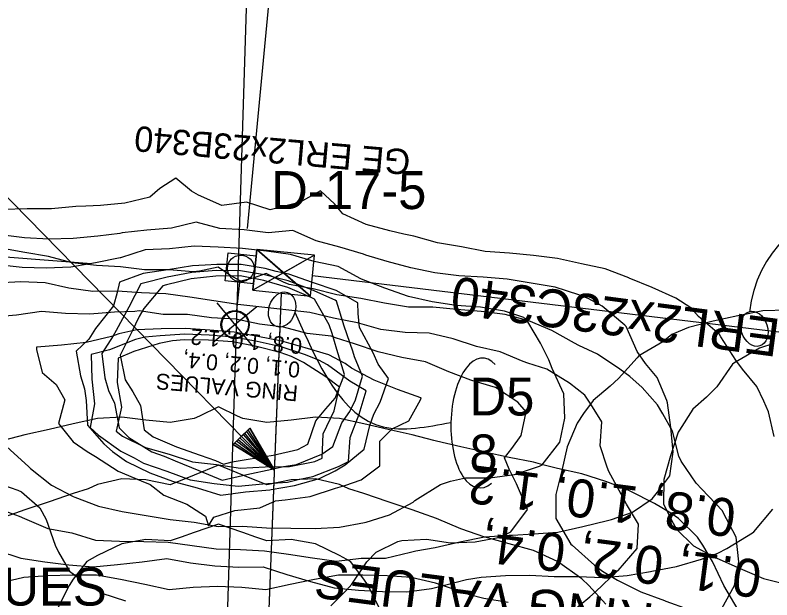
# Model space of a CAD drawing. Extents: x 1638506 to 1658005, y 834807 to 846788.
# Drawn here: x 1642396.4 to 1642635.4, y 842263.3 to 842448.1 of the extents above; entities that cross this region are included whole.
import ezdxf

# ---------------------------------------------------------------- set-up
doc = ezdxf.new("R2010")
doc.units = 0
for name, color, linetype in [('Default', 7, 'Continuous'), ('Old_Level_1', 7, 'Continuous'), ('Old_Level_2', 7, 'Continuous'), ('Scratch_Level_0', 7, 'Continuous')]:
    doc.layers.add(name, color=color, linetype=linetype)

msp = doc.modelspace()

# ---------------------------------------------------------------- linework, layer by layer
at = {"layer": 'Default'}
for p, q in [((1642469.76, 842380.62), (1642481.25, 842500.55)), ((1642342.93, 842442.48), (1642478.26, 842304.41)), ((1642490.95, 842372.22), (1642471.46, 842361.16)), ((1642489.65, 842359.32), (1642472.76, 842374.05)), ((1642490.3, 842365.77), (1642742.03, 842335.36)), ((1642467.21, 842363.62), (1642466.31, 842354.72)), ((1642473.12, 842172.77), (1642480.55, 842360.24)), ((1642472.77, 842355.93), (1642458.93, 842344.63)), ((1642471.53, 842343.36), (1642460.2, 842357.2)), ((1642469.35, 842353.14), (1642469.35, 842353.14)), ((1642465.86, 842350.27), (1642465.86, 842350.27)), ((1642473.28, 842176.7), (1642480.22, 842351.8))]:
    msp.add_line(p, q, dxfattribs=at)
for points in [[(1642472.55, 842372.04), (1642471.66, 842363.17), (1642462.76, 842364.07), (1642463.65, 842372.94)], [(1642490.95, 842372.22), (1642472.76, 842374.05), (1642471.46, 842361.16), (1642489.65, 842359.32)], [(1642481.2, 842366.69), (1642471.46, 842361.16), (1642472.76, 842374.05)], [(1642481.2, 842366.69), (1642489.65, 842359.32), (1642490.95, 842372.22)]]:
    msp.add_lwpolyline(points, close=True, dxfattribs=at)
msp.add_lwpolyline([(1642467.9, 842314.98), (1642468.43, 842315.5), (1642478.26, 842304.41), (1642468.92, 842315.98), (1642469.45, 842316.5), (1642478.26, 842304.41), (1642469.98, 842317.02), (1642470.51, 842317.53), (1642478.26, 842304.41), (1642465.3, 842312.36), (1642465.79, 842312.91), (1642478.26, 842304.41), (1642466.35, 842313.39), (1642466.85, 842313.94), (1642478.26, 842304.41), (1642467.37, 842314.46), (1642470.51, 842317.53), (1642465.3, 842312.36), (1642478.26, 842304.41), (1642470.51, 842317.53)], dxfattribs=at)
msp.add_circle((1642465.86, 842350.3), 4.47, dxfattribs=at)
for centre, major_axis, ratio, start_param, end_param in [((1642658, 842350.99), (-3.78, -34.34), 0.862742, 3.141593, 4.712389), ((1642543.62, 842319.15), (-0.49, -20.52), 0.466223, 2.710831, 4.712389), ((1642543.62, 842319.15), (-0.49, -20.52), 0.466223, 4.712389, 6.681485)]:
    msp.add_ellipse(centre, major_axis=major_axis, ratio=ratio, start_param=start_param, end_param=end_param, dxfattribs=at)
for centre, major_axis in [((1642480.71, 842355.05), (1.72, 5.4)), ((1642629.94, 842348.95), (1.72, -5.4))]:
    msp.add_ellipse(centre, major_axis=major_axis, ratio=0.730797, dxfattribs=at)
msp.add_spline([(1642484.79, 842354.24), (1642512.62, 842317.96), (1642534.05, 842319.37)], degree=3, dxfattribs=at)
at = {"layer": 'Old_Level_1'}
for points in [[(1642636.21, 842314.91), (1642634.39, 842322.75), (1642632.93, 842326.11), (1642630.72, 842330.75), (1642626.13, 842336.15), (1642624.01, 842339.02), (1642619.35, 842346.46), (1642618.9, 842347.14), (1642612.23, 842352.84), (1642609.85, 842355.61), (1642605.06, 842358.67), (1642597.68, 842362.03), (1642590.31, 842365), (1642590.26, 842365.02), (1642582.83, 842367.91), (1642575.29, 842369.54), (1642567.75, 842371.13), (1642560.16, 842372.13), (1642552.55, 842372.84), (1642544.91, 842373.35), (1642537.36, 842374.85), (1642529.8, 842376.17), (1642522.3, 842378.24), (1642519.22, 842378.9), (1642514.77, 842379.93), (1642507.27, 842381.97), (1642499.88, 842385.29), (1642497.26, 842388.5), (1642492.84, 842392.62), (1642487.21, 842389.38), (1642484.8, 842388.53), (1642476.96, 842386.61), (1642469.48, 842388.96), (1642461.72, 842387.94), (1642454.32, 842391.19), (1642452.1, 842392.45), (1642447.12, 842396.62), (1642442.05, 842393.33), (1642438.91, 842390.62), (1642431.06, 842388.64), (1642423.32, 842387.93), (1642418.76, 842387.69), (1642415.61, 842387.57), (1642407.86, 842386.84), (1642400.19, 842386.86), (1642392.49, 842386.69)], [(1642391.88, 842291.85), (1642397.64, 842289.71), (1642399.3, 842288.97), (1642406.7, 842285.78), (1642414.26, 842284.44), (1642421.74, 842282.13), (1642429.4, 842281.83), (1642437.06, 842281.68), (1642444.72, 842281.45), (1642452.31, 842280.47), (1642459.9, 842279.41), (1642467.56, 842279.14), (1642475.2, 842278.79), (1642482.79, 842277.68), (1642490.36, 842276.5), (1642497.95, 842275.46), (1642505.71, 842276.43), (1642513.39, 842276.44), (1642521.24, 842278.3), (1642523, 842278.74), (1642529.05, 842279.85), (1642536.89, 842281.65), (1642544.7, 842283.16), (1642552.42, 842283.66), (1642553.54, 842283.75), (1642560.14, 842284.14), (1642567.87, 842284.68), (1642575.7, 842286.46), (1642583.55, 842288.38), (1642584.82, 842288.69), (1642591.46, 842290.98), (1642597.65, 842295.25), (1642599.73, 842297.8), (1642603.17, 842302.44), (1642604.31, 842310.02), (1642603.54, 842317.77), (1642602.51, 842325.54), (1642602.23, 842326.27), (1642599.17, 842333.51), (1642595.57, 842337.97), (1642592.9, 842341.74), (1642589.38, 842349.72), (1642588.95, 842350.12), (1642581.8, 842356.15), (1642577.66, 842358.43), (1642574.44, 842359.73), (1642566.96, 842362.11), (1642559.4, 842363.41), (1642551.83, 842364.63), (1642544.21, 842365.31), (1642536.56, 842365.68), (1642528.97, 842366.65), (1642521.42, 842368.19), (1642513.92, 842370.27), (1642507.13, 842372.28), (1642506.45, 842372.58), (1642498.96, 842374.79), (1642491.46, 842376.8), (1642484.06, 842380.03), (1642476.32, 842379.3), (1642468.72, 842380.26), (1642461.08, 842380.63), (1642453.58, 842382.7), (1642445.73, 842380.8), (1642437.99, 842380.12), (1642430.24, 842379.25), (1642429.51, 842379.07), (1642422.47, 842378.27), (1642414.73, 842377.53), (1642407.03, 842377.32), (1642399.38, 842377.68), (1642391.79, 842378.64)], [(1642393.62, 842311.77), (1642400.74, 842305.35), (1642401.21, 842304.75), (1642407.9, 842299.52), (1642414.69, 842295.89), (1642415.25, 842295.68), (1642422.68, 842292.89), (1642430.21, 842291.16), (1642437.78, 842289.94), (1642445.35, 842288.7), (1642452.96, 842287.87), (1642460.52, 842286.47), (1642468.2, 842286.54), (1642475.84, 842286.03), (1642483.51, 842285.94), (1642491.18, 842285.82), (1642498.89, 842286.22), (1642506.7, 842287.68), (1642507.29, 842287.79), (1642514.6, 842290.18), (1642522.1, 842294.18), (1642522.67, 842294.68), (1642530.79, 842299.77), (1642533.92, 842300.82), (1642538.65, 842301.79), (1642546.34, 842301.86), (1642554.11, 842302.92), (1642562.02, 842305.57), (1642562.93, 842305.96), (1642568.5, 842313.16), (1642570.09, 842320.7), (1642569.7, 842328.41), (1642566.08, 842336.4), (1642564.95, 842339.11), (1642562.31, 842344.41), (1642558.33, 842351.16), (1642557.11, 842352.55), (1642550.94, 842354.51), (1642543.38, 842355.8), (1642535.74, 842356.33), (1642528.16, 842357.43), (1642520.63, 842359.14), (1642513.19, 842361.85), (1642505.76, 842364.68), (1642505.63, 842364.73), (1642498.42, 842368.6), (1642490.89, 842370.26), (1642483.39, 842372.4), (1642475.81, 842373.48), (1642468.2, 842374.31), (1642460.57, 842374.81), (1642452.91, 842375.07), (1642445.16, 842374.26), (1642437.45, 842373.93), (1642429.68, 842371.38), (1642429.55, 842371.34), (1642421.74, 842369.85), (1642413.94, 842368.47), (1642406.22, 842368.09), (1642398.57, 842368.33), (1642390.96, 842369.14)], [(1642416.98, 842334.09), (1642418.25, 842329.97), (1642418.84, 842326.25), (1642419.28, 842318.53), (1642424.41, 842312.61), (1642427.12, 842310.17), (1642431.6, 842306.98), (1642438.96, 842303.37), (1642446.08, 842300.83), (1642446.41, 842300.73), (1642453.91, 842298.71), (1642461.38, 842296.34), (1642469.15, 842297.38), (1642476.89, 842298.06), (1642477.23, 842298.1), (1642484.68, 842299.37), (1642492.56, 842301.65), (1642497.52, 842304.01), (1642500.62, 842305.95), (1642506.69, 842310.88), (1642508.47, 842318.41), (1642509.7, 842321.97), (1642511.66, 842325.81), (1642514.33, 842333.25), (1642511.08, 842337.73), (1642509.52, 842341.35), (1642505.17, 842349.41), (1642504.8, 842353.76), (1642504.65, 842357.14), (1642497.77, 842361.11), (1642490.31, 842363.63), (1642482.85, 842366.21), (1642478.85, 842367.07), (1642475.33, 842367.98), (1642467.77, 842369.32), (1642460.09, 842369.31), (1642456.46, 842369.03), (1642452.37, 842368.88), (1642444.58, 842367.63), (1642436.8, 842366.45), (1642429.32, 842363.73), (1642428.59, 842360.43), (1642427.47, 842356.21), (1642421.79, 842349.03), (1642419.63, 842345.73), (1642415.65, 842341.89), (1642416.98, 842334.09)], [(1642424.68, 842333.42), (1642425.88, 842329.43), (1642427.75, 842325.47), (1642429.23, 842317.66), (1642432.26, 842314.61), (1642439.54, 842310.05), (1642443.48, 842308.73), (1642446.98, 842307.23), (1642454.39, 842304.18), (1642461.8, 842301.13), (1642469.63, 842302.85), (1642477.46, 842304.56), (1642481.16, 842305.44), (1642485.27, 842306.05), (1642493.23, 842309.28), (1642496.74, 842311.75), (1642499.56, 842319.19), (1642502.09, 842322.76), (1642503.96, 842326.48), (1642506.17, 842333.97), (1642503.6, 842340.07), (1642503.06, 842341.92), (1642500.36, 842349.83), (1642497.89, 842357.73), (1642497.49, 842357.96), (1642490.1, 842361.23), (1642482.67, 842364.13), (1642475.16, 842366.01), (1642467.59, 842367.27), (1642459.91, 842367.34), (1642452.19, 842366.79), (1642444.37, 842365.23), (1642436.52, 842363.29), (1642436.09, 842363.14), (1642432.28, 842355.79), (1642428.25, 842348.46), (1642427.39, 842346.74), (1642423.81, 842341.17), (1642424.68, 842333.42)], [(1642431.15, 842332.85), (1642433.52, 842328.98), (1642435.94, 842324.75), (1642437.1, 842316.97), (1642439.96, 842314.8), (1642447.36, 842311.68), (1642454.81, 842309.03), (1642459.7, 842307.32), (1642462.24, 842306.14), (1642464.94, 842306.86), (1642470.05, 842307.69), (1642477.85, 842309.01), (1642485.68, 842310.79), (1642488.88, 842312.44), (1642491.37, 842319.9), (1642494.49, 842323.64), (1642497.49, 842327.05), (1642500.39, 842334.47), (1642498.01, 842342.36), (1642496.57, 842347.49), (1642495.63, 842350.25), (1642490.96, 842358.33), (1642489.88, 842358.82), (1642482.49, 842362.04), (1642475, 842364.25), (1642467.45, 842365.69), (1642459.76, 842365.59), (1642452, 842364.71), (1642444.16, 842362.82), (1642443.01, 842362.53), (1642437.02, 842355.38), (1642435.61, 842352.82), (1642433.3, 842348.02), (1642429.59, 842340.67), (1642431.15, 842332.85)], [(1642640.27, 842354.88), (1642632.57, 842354.59), (1642624.75, 842353.04), (1642624.7, 842353.02), (1642616.93, 842351.38), (1642609.07, 842349.35), (1642603.82, 842347.17), (1642601, 842344.85), (1642593.44, 842340.4), (1642592.88, 842339.81), (1642586.99, 842333.28), (1642584.41, 842330.83), (1642578.95, 842326.31), (1642575.97, 842322.13), (1642573.95, 842319.07), (1642570.79, 842311.66), (1642569.07, 842304.14), (1642567.18, 842296.62), (1642567.24, 842288.94), (1642571.96, 842280.85)], [(1642636.02, 842344.35), (1642631.54, 842342.83), (1642623.45, 842338.14), (1642622.96, 842337.82), (1642618.1, 842330.56), (1642614.82, 842327.32), (1642610.51, 842323.55), (1642606.24, 842316.95), (1642605.83, 842316.28), (1642603.46, 842308.81), (1642601.36, 842301.31), (1642601.17, 842293.65)], [(1642601.17, 842293.65), (1642603.75, 842288.48), (1642605.35, 842285.6), (1642610.71, 842280.33), (1642616.85, 842276.92), (1642618.05, 842276.4), (1642625.44, 842273.14), (1642632.85, 842270.03), (1642640.36, 842268.15)], [(1642390.74, 842278.87), (1642398.21, 842276.45), (1642405.78, 842275.24), (1642413.38, 842274.35), (1642421, 842273.69), (1642428.74, 842274.4), (1642436.5, 842275.31), (1642444.27, 842276.36), (1642451.83, 842274.94), (1642459.42, 842273.98), (1642467.07, 842273.6), (1642474.76, 842273.69), (1642482.23, 842271.31), (1642489.71, 842269.07), (1642497.21, 842267.02), (1642504.83, 842266.35), (1642512.47, 842265.91), (1642520.14, 842265.78), (1642527.92, 842266.87), (1642535.76, 842268.8), (1642539, 842269.66), (1642543.58, 842270.41), (1642551.31, 842270.96), (1642559, 842271.08), (1642566.64, 842270.62), (1642574.32, 842270.68), (1642581.98, 842270.36), (1642589.7, 842270.93), (1642597.06, 842272.26), (1642597.51, 842272.35), (1642605.31, 842273.77), (1642613.2, 842276.13), (1642618.4, 842278.07), (1642621.17, 842279.51), (1642629.29, 842284.49), (1642629.71, 842284.76), (1642635.76, 842291.91)], [(1642571.96, 842280.85), (1642572.33, 842280.5), (1642579.46, 842274.19), (1642581.94, 842272.29), (1642586.72, 842269.48), (1642594.08, 842265.78), (1642601.52, 842263.03), (1642601.94, 842262.86), (1642608.96, 842260.27), (1642616.47, 842258.37), (1642624.06, 842257.35), (1642631.62, 842255.97), (1642639.22, 842255.09)], [(1642552.11, 842262.46), (1642544.46, 842263.68), (1642539.96, 842264.82), (1642536.81, 842265.97), (1642529.16, 842268.57), (1642521.51, 842270.33), (1642513.86, 842270.87), (1642506.21, 842271.1), (1642498.56, 842271.1), (1642490.91, 842269.71), (1642483.26, 842268.13), (1642475.61, 842266.41), (1642467.96, 842267.17), (1642460.31, 842267.46), (1642452.66, 842267.17), (1642445.01, 842266.41), (1642437.36, 842268.13), (1642429.71, 842269.71), (1642422.06, 842271.1), (1642414.41, 842271.1), (1642406.76, 842270.87), (1642399.11, 842270.33), (1642391.46, 842268.57)]]:
    msp.add_lwpolyline(points, dxfattribs=at)
msp.add_circle((1642467.66, 842368.05), 4.21, dxfattribs=at)
at = {"layer": 'Old_Level_2'}
msp.add_line((1642458.82, 842108.44), (1642469.85, 842461.62), dxfattribs=at)
msp.add_lwpolyline([(1642025.39, 842444.99), (1642047.66, 842437.99), (1642090.85, 842425.3), (1642111.35, 842420.03), (1642135.93, 842413.98), (1642180.4, 842403.97), (1642212.86, 842397.26), (1642258.65, 842389.41), (1642289.59, 842384.48), (1642317.7, 842380.48), (1642343.73, 842376.94), (1642368.27, 842374.07), (1642394.7, 842371.65), (1642420.5, 842369.62)], dxfattribs=at)
at = {"layer": 'Scratch_Level_0'}
for points in [[(1642619.64, 842260.56), (1642623.63, 842267.75), (1642625.02, 842275.28), (1642624.13, 842283.12), (1642620.08, 842290.93), (1642619.85, 842291.4), (1642613.34, 842298.29), (1642611.58, 842300.2), (1642606.78, 842307.09), (1642606.09, 842308.64), (1642604.07, 842316.62), (1642601.03, 842322.04), (1642599.35, 842324.96), (1642594.42, 842330.4), (1642590.59, 842333.83), (1642587.46, 842336.17), (1642580.38, 842340.98), (1642574.45, 842343.67), (1642573.11, 842344.38), (1642565.93, 842348.42), (1642558.62, 842351.5), (1642551.16, 842353.45), (1642543.58, 842354.46), (1642535.94, 842355.06), (1642528.32, 842355.81), (1642520.61, 842355.82), (1642513.05, 842357.03), (1642505.54, 842358.58), (1642497.96, 842359.66), (1642490.51, 842361.61), (1642482.97, 842362.99), (1642481.12, 842363.69), (1642475.71, 842366.48), (1642471.57, 842364.95), (1642467.67, 842363.97), (1642464.16, 842365.92), (1642460.55, 842368.47), (1642454.6, 842367.18), (1642452.63, 842366.98), (1642445, 842367.61), (1642437.29, 842367.65), (1642429.69, 842368.57), (1642422.04, 842369.02), (1642414.43, 842369.81), (1642406.97, 842371.8), (1642399.42, 842373.05), (1642391.89, 842374.44)], [(1642571.87, 842259.14), (1642577.98, 842264.21), (1642579.74, 842265.82), (1642586.79, 842272.53), (1642586.86, 842272.59), (1642592.89, 842279.52), (1642593.29, 842287.18), (1642589.56, 842293.56), (1642588.5, 842295.53), (1642583.97, 842303.84), (1642583.38, 842305.19), (1642581.24, 842311.92), (1642581.77, 842319.56), (1642578.3, 842325.17), (1642576.33, 842327.99), (1642571.46, 842331.8), (1642564.32, 842336.19), (1642558.32, 842338.08), (1642556.92, 842338.63), (1642549.61, 842341.69), (1642542.11, 842343.36), (1642534.72, 842345.8), (1642527.23, 842347.53), (1642519.55, 842347.79), (1642511.96, 842348.78), (1642504.52, 842350.87), (1642497, 842352.34), (1642489.51, 842354.07), (1642481.91, 842354.95), (1642474.3, 842355.75), (1642466.71, 842356.69), (1642459.13, 842357.75), (1642451.57, 842358.95), (1642444.01, 842360.06), (1642436.33, 842360.34), (1642428.68, 842360.86), (1642420.95, 842360.77), (1642413.37, 842361.78), (1642405.88, 842363.52), (1642398.2, 842363.79), (1642390.42, 842363.35)], [(1642496.16, 842261.4), (1642501.1, 842266.37), (1642502.7, 842268.25), (1642507.53, 842275.33), (1642510.4, 842278.38), (1642517.33, 842281.76), (1642518.59, 842281.98), (1642526.37, 842282.47), (1642533.93, 842281.26), (1642541.69, 842281.61), (1642549.6, 842283.05), (1642553.03, 842284.77), (1642558.21, 842291.8), (1642554.72, 842299.98), (1642552.44, 842304.59), (1642550.93, 842308.19), (1642553.3, 842311.13), (1642556.23, 842315.21), (1642557.87, 842322.71), (1642555.23, 842325.76), (1642548.13, 842330.43), (1642540.7, 842332.62), (1642540.35, 842332.74), (1642533.34, 842335.32), (1642526.04, 842338.46), (1642518.5, 842339.85), (1642511.02, 842341.63), (1642503.64, 842344.2), (1642497.55, 842346.09), (1642496.25, 842346.62), (1642488.64, 842347.47), (1642481.2, 842349.52), (1642473.61, 842350.47), (1642466.09, 842352.01), (1642458.44, 842352.47), (1642450.86, 842353.52), (1642443.14, 842353.47), (1642435.57, 842354.62), (1642434.18, 842354.44), (1642427.8, 842354.19), (1642420.01, 842353.62), (1642412.32, 842353.84), (1642404.69, 842354.45), (1642396.82, 842353.31), (1642389.37, 842352.63)], [(1642403.1, 842343.1), (1642403.1, 842342.45), (1642404.95, 842335.15), (1642409.36, 842331.35), (1642412.13, 842326.48), (1642410.1, 842319.03), (1642414.68, 842313.19), (1642419.18, 842310.12), (1642421.79, 842308.59), (1642428.9, 842303.97), (1642436.21, 842300.87), (1642439.09, 842299.78), (1642443.33, 842296.4), (1642450.67, 842293.55), (1642456.55, 842289.77), (1642457.48, 842286.69), (1642459.18, 842289.42), (1642465.84, 842291.55), (1642473.67, 842292.4), (1642478.64, 842294.57), (1642481.71, 842294.88), (1642489.57, 842295.98), (1642497.63, 842298.59), (1642500.55, 842299.4), (1642505.69, 842301.2), (1642511.63, 842305.66), (1642511.59, 842313.38), (1642515.54, 842317.36), (1642520.78, 842319.88), (1642524.45, 842326.46), (1642524.63, 842327.09), (1642524.54, 842327.14), (1642517.18, 842329.79), (1642509.84, 842332.67), (1642502.63, 842336.54), (1642500.64, 842337.97), (1642495.46, 842340.69), (1642488.05, 842342.96), (1642480.61, 842345.09), (1642473.08, 842346.48), (1642465.54, 842347.84), (1642457.91, 842348.48), (1642450.28, 842349.09), (1642442.54, 842348.96), (1642434.79, 842348.68), (1642429.09, 842347.4), (1642426.79, 842346.53), (1642418.83, 842344.66), (1642411, 842343.78), (1642403.19, 842343.13), (1642403.1, 842343.1)], [(1642420.06, 842317.72), (1642422.68, 842315.37), (1642429.73, 842310.29), (1642433.95, 842308.18), (1642436.94, 842306.47), (1642444.32, 842303.91), (1642451.68, 842301.23), (1642459.24, 842300.04), (1642466.85, 842299.23), (1642474.66, 842299.91), (1642482.45, 842300.47), (1642485.78, 842301.35), (1642490.41, 842302.29), (1642498.53, 842305.37), (1642501.67, 842306.97), (1642502.25, 842314.61), (1642505.1, 842321.95), (1642507.28, 842329.38), (1642502.08, 842332.35), (1642495.05, 842337.55), (1642492.33, 842339.06), (1642487.76, 842340.78), (1642480.38, 842343.3), (1642472.87, 842344.9), (1642465.35, 842346.36), (1642457.7, 842346.9), (1642450.04, 842347.3), (1642442.25, 842346.77), (1642437.4, 842346.3), (1642434.38, 842345.54), (1642426.24, 842342.34), (1642420.44, 842340.82), (1642420.63, 842333.08), (1642421.48, 842325.25), (1642420.06, 842317.72)], [(1642428.34, 842316.63), (1642430.35, 842315.01), (1642437.6, 842311.46), (1642445.04, 842309.36), (1642452.43, 842306.85), (1642460.04, 842306.05), (1642467.59, 842304.85), (1642475.38, 842305.36), (1642483.11, 842305.46), (1642491.03, 842307.02), (1642493.39, 842308.06), (1642493.73, 842315.73), (1642497.16, 842322.99), (1642498.84, 842330.49), (1642494.56, 842333.81), (1642487.44, 842338.35), (1642483.65, 842340.21), (1642480.14, 842341.5), (1642472.66, 842343.33), (1642465.15, 842344.87), (1642457.5, 842345.33), (1642449.8, 842345.5), (1642446.07, 842345.16), (1642441.93, 842344.34), (1642433.88, 842341.81), (1642428.89, 842339.71), (1642428.57, 842332.03), (1642430, 842324.13), (1642428.34, 842316.63)], [(1642624.81, 842260.1), (1642621.29, 842265.98), (1642620.3, 842267.75), (1642616.7, 842275.4), (1642613.64, 842280.54), (1642611.92, 842283.05), (1642605.99, 842288.95), (1642603.56, 842290.7), (1642598.34, 842293.69), (1642590.69, 842297.59), (1642589.11, 842298.35), (1642583.04, 842300.64), (1642575.39, 842303.11), (1642567.74, 842304.74), (1642563.05, 842306), (1642560.09, 842306.81), (1642552.44, 842308.23), (1642544.79, 842309.92), (1642537.14, 842311.62), (1642529.49, 842313.46), (1642528.68, 842313.65), (1642521.84, 842315.38), (1642514.19, 842317.14), (1642506.54, 842318.95), (1642498.89, 842320.56), (1642491.24, 842321.06), (1642483.59, 842320.06), (1642475.94, 842319.37), (1642468.29, 842320.59), (1642466.6, 842321.3), (1642460.64, 842324.28), (1642454.67, 842321.3), (1642452.99, 842320.59), (1642445.34, 842319.37), (1642437.69, 842320.06), (1642430.04, 842321.06), (1642422.39, 842320.56), (1642414.74, 842318.95), (1642407.09, 842317.14), (1642399.44, 842315.38), (1642392.59, 842313.65)], [(1642583.04, 842261.93), (1642577.64, 842267.75), (1642575.39, 842269.87), (1642567.74, 842275.38), (1642567.7, 842275.4), (1642560.09, 842278.9), (1642552.44, 842280.97), (1642544.82, 842283.05), (1642544.79, 842283.06), (1642537.14, 842285.75), (1642529.49, 842288.98), (1642524.74, 842290.7), (1642521.84, 842291.73), (1642514.19, 842294.24), (1642506.54, 842296.88), (1642501.84, 842298.35), (1642498.89, 842299.68), (1642491.24, 842301.47), (1642483.59, 842301.19), (1642475.94, 842299.65), (1642468.29, 842302.63), (1642460.64, 842305.81), (1642452.99, 842302.63), (1642445.34, 842299.65), (1642437.69, 842301.19), (1642430.04, 842301.47), (1642422.39, 842299.68), (1642419.43, 842298.35), (1642414.74, 842296.88), (1642407.09, 842294.24), (1642399.44, 842291.73), (1642396.53, 842290.7), (1642391.79, 842288.98)], [(1642389.85, 842300.46), (1642397.24, 842297.97), (1642398.4, 842297.43), (1642404.22, 842292.38), (1642406.2, 842288.68), (1642409.03, 842280.59), (1642410.09, 842278.36), (1642413.58, 842272.28), (1642416.7, 842269.99), (1642423.81, 842265.36), (1642431.21, 842262.95)], [(1642511.74, 842260.1), (1642507.88, 842267.75), (1642506.54, 842269.83), (1642502.28, 842275.4), (1642498.89, 842277.27), (1642491.24, 842280.92), (1642483.59, 842282.35), (1642475.94, 842281.95), (1642472.43, 842283.05), (1642468.29, 842284.56), (1642460.64, 842287.16), (1642452.99, 842284.56), (1642448.84, 842283.05), (1642445.34, 842281.95), (1642437.69, 842282.35), (1642430.04, 842280.92), (1642422.39, 842277.27), (1642418.99, 842275.4), (1642414.74, 842269.83), (1642413.4, 842267.75), (1642409.54, 842260.1)]]:
    msp.add_lwpolyline(points, dxfattribs=at)
msp.add_circle((1642465.86, 842350.27), 4.21, dxfattribs=at)

# ---------------------------------------------------------------- texts
at = {"layer": 'Default'}
for s, p in [('D-17-5', (1642477.26, 842386.81)), ('D5', (1642539.91, 842321.55)), ('8', (1642539.91, 842303.55))]:
    msp.add_text(s, height=12, dxfattribs=at).set_placement(p)
at = {"layer": 'Old_Level_1'}
for s, height, p in [('GE ERL2x23B340', 8, (1642521.54, 842405.52)), ('0.8, 1.0, 1.2', 5, (1642487.22, 842345.91)), ('0.1, 0.2, 0.4,', 5, (1642486.57, 842338.44)), ('RING VALUES', 5, (1642485.92, 842330.97))]:
    msp.add_text(s, height=height, rotation=175, dxfattribs=at).set_placement(p)
at = {"layer": 'Scratch_Level_0'}
for s, p in [('GE ERL2x23C340', (1642665.94, 842348.34)), ('0.8, 1.0, 1.2', (1642624.61, 842294.86)), ('0.1, 0.2, 0.4,', (1642632.75, 842275.63)), ('RING VALUES', (1642598.7, 842261.96))]:
    msp.add_text(s, height=12, rotation=172.4934, dxfattribs=at).set_placement(p)
msp.add_text('RING VALUES', height=12, dxfattribs=at).set_placement((1642317.41, 842261.45))

doc.saveas('drawing.dxf')
